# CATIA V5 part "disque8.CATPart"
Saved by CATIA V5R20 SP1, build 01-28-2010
Part number: disque1.1.2
Bounding box of the stored display mesh (mm): x 56 to 104, y 0 to 5, z 76.175 to 123.825
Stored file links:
  E:\EDELI\gcausse\Edeli_2012_233_gcausse\disque8.CATPart
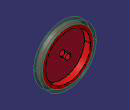
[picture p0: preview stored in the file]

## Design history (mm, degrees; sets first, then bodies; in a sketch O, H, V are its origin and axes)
Body1 (main body)
  DatumSurface1
  Sketch1 on face of DatumSurface1, origin (0, 5, 0), H (1, 0, 0), V (0, 0, 1)
    circle A1 centre (80, 100) radius 19
    circle A2 centre (80, 100) radius 2.5
    radius A1 = 19
    radius A2 = 2.5
  Pad1: profile Sketch1, direction (0, -1, 0), length 5
Body2
  Sketch2 on start face of Pad1, origin (0, 5, 0), H (-1, 0, 0), V (0, 0, 1)
    circle A1 centre (-80, 100) radius 21.5
    circle A2 centre (-80, 100) radius 19
    radius A2 = 19
    radius A1 = 21.5
  Pad2: profile Sketch2, direction (0, -1, 0), length 5
  Sketch3 on start face of Pad1, origin (0, 5, 0), H (-1, 0, 0), V (0, 0, 1)
Body3
  Sketch4 on start face of Pad1, origin (0, 5, 0), H (-1, 0, 0), V (0, 0, 1)
    circle A1 centre (-80, 100) radius 24
    circle A2 centre (-80, 100) radius 21.5
    radius A2 = 21.5
    radius A1 = 24
  Pad3: profile Sketch4, direction (0, -1, 0), length 5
